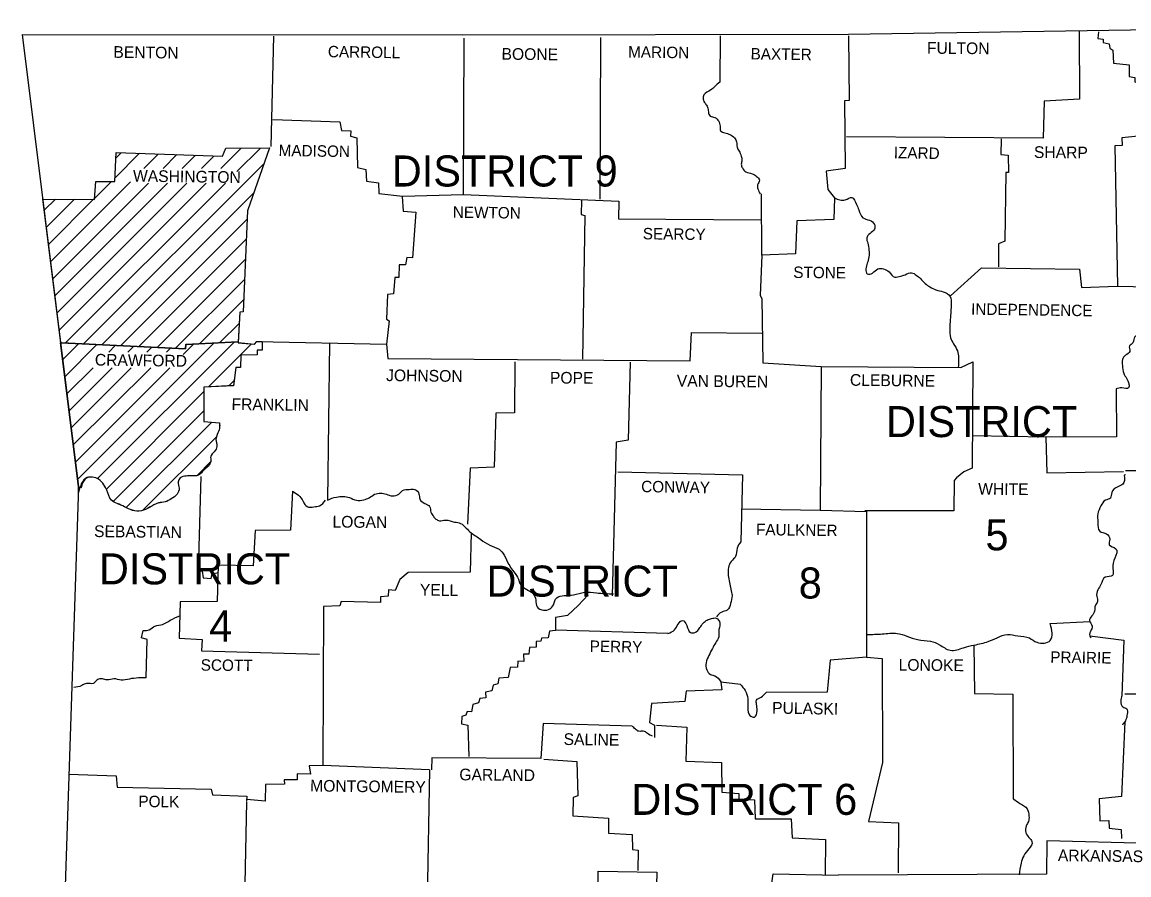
# Model space of a CAD drawing. Extents: x 21307 to 29830, y 1322443 to 1332359.
# Drawn here: x 24969 to 25700, y 1330891 to 1331455 of the extents above; entities that cross this region are included whole.
import ezdxf

# ---------------------------------------------------------------- set-up
doc = ezdxf.new("R2010")
doc.units = 0
doc.layers.add('R_Draft', color=7, linetype='Continuous')

msp = doc.modelspace()

# ---------------------------------------------------------------- linework, layer by layer
at = {"layer": 'R_Draft'}
for p, q in [((25698.3, 1331158.83), (25719.72, 1331158.83)), ((25238.04, 1330960.83), (25235.94, 1330847.79))]:
    msp.add_line(p, q, dxfattribs=at)
for points in [[(24968.58, 1331447.01), (25259.64, 1331446.83), (25515.06, 1331447.37), (25816.38, 1331452.05), (25956.06, 1331455.29)], [(24968.58, 1331447.01), (25005.84, 1331147.85), (24989.64, 1330659.51)], [(25134.72, 1331445.93), (25133.1, 1331373.03)], [(25134.36, 1331390.85), (25178.64, 1331389.41), (25179.72, 1331383.65), (25185.84, 1331383.47), (25185.66, 1331379.87), (25189.98, 1331378.79), (25190.34, 1331359.17), (25195.92, 1331357.91), (25196.28, 1331350.17), (25204.2, 1331349.09), (25204.56, 1331341.89), (25220.22, 1331340.27), (25260.54, 1331341.17), (25260.9, 1331444.67)], [(25351.08, 1331445.03), (25350.54, 1331338.11)], [(25430.28, 1331446.29), (25429.92, 1331415.51)], [(25515.06, 1331446.29), (25515.42, 1331403.45), (25512.36, 1331403.27), (25512.9, 1331358.45), (25500.3, 1331356.65), (25501.38, 1331344.59), (25505.7, 1331339.01), (25505.34, 1331324.79), (25480.86, 1331323.89), (25479.96, 1331301.93), (25457.64, 1331301.21), (25456.56, 1331274.57), (25457.82, 1331272.41), (25458.36, 1331229.93), (25496.88, 1331227.41), (25496.34, 1331132.55), (25526.94, 1331131.65), (25526.94, 1331035.17), (25502.82, 1331033.37), (25501.02, 1331012.13), (25460.52, 1331011.95)], [(25667.52, 1331448.99), (25667.88, 1331404.35), (25644.48, 1331403.09), (25643.76, 1331378.61), (25513.62, 1331379.33)], [(25680.48, 1331448.81), (25679.94, 1331444.49), (25683.54, 1331443.95), (25683.36, 1331441.79), (25687.5, 1331440.89), (25687.86, 1331438.01), (25689.84, 1331436.75), (25690.38, 1331428.11), (25700.64, 1331427.03), (25700.64, 1331419.29), (25704.42, 1331418.75), (25704.42, 1331415.69), (25707.66, 1331414.79), (25707.48, 1331404.35), (25710.36, 1331403.81), (25711.08, 1331380.23), (25695.78, 1331378.79), (25695.96, 1331373.75), (25691.28, 1331373.57), (25692.9, 1331280.69), (25765.44, 1331279.07), (25766.7, 1331134.71), (25719.36, 1331133.45), (25718.46, 1331157.75)], [(25616.04, 1331378.07), (25615.68, 1331367.63), (25620.72, 1331367.27), (25620.9, 1331355.75), (25619.1, 1331355.75), (25618.38, 1331310.39), (25614.24, 1331308.59), (25614.24, 1331293.47)], [(24982.8, 1331338.11), (25016.46, 1331337.93), (25017.36, 1331349.81), (25029.78, 1331349.81), (25030.86, 1331369.07), (25101.06, 1331366.55), (25103.22, 1331371.95), (25132.2, 1331372.13), (25117.62, 1331330.37), (25114.74, 1331263.59), (25112.58, 1331263.41), (25111.5, 1331243.25), (25122.12, 1331242.35), (25123.74, 1331243.97), (25209.6, 1331242.35), (25210.5, 1331232.81)], [(24982.8, 1331338.11), (25016.46, 1331337.93), (25017.36, 1331349.81), (25029.78, 1331349.81), (25030.86, 1331369.07), (25101.06, 1331366.55), (25103.22, 1331371.95), (25132.2, 1331372.13), (25117.62, 1331330.37), (25114.74, 1331263.59), (25112.58, 1331263.41), (25111.5, 1331243.79)], [(25099.98, 1331358.45), (25113.48, 1331371.95)], [(25110.6, 1331356.47), (25126.26, 1331371.95)], [(25029.96, 1331352.15), (25046.16, 1331368.53)], [(25030.68, 1331365.47), (25034.1, 1331368.89)], [(25049.04, 1331358.45), (25058.58, 1331367.99)], [(25061.82, 1331358.45), (25070.82, 1331367.63)], [(25074.42, 1331358.45), (25083.24, 1331367.27)], [(25087.2, 1331358.45), (25095.3, 1331366.73)], [(25009.26, 1331242.53), (25128.42, 1331361.51)], [(24987.48, 1331296.89), (25040.22, 1331349.63)], [(24988.92, 1331285.55), (25052.1, 1331348.73)], [(24990.36, 1331274.39), (25064.7, 1331348.73)], [(24991.8, 1331263.05), (25077.48, 1331348.73)], [(24993.24, 1331251.71), (25090.26, 1331348.73)], [(24997.2, 1331243.07), (25103.04, 1331348.73)], [(25016.64, 1331338.83), (25027.62, 1331349.81)], [(25021.5, 1331241.99), (25121.58, 1331342.07)], [(25260.54, 1331341.17), (25363.14, 1331336.85), (25362.96, 1331325.15), (25457.1, 1331324.43)], [(25457.64, 1331301.21), (25457.46, 1331341.71)], [(24994.14, 1331243.07), (24982.26, 1331338.11)], [(24983.16, 1331330.91), (24990.54, 1331338.11)], [(24984.6, 1331319.57), (25003.14, 1331338.11)], [(24986.04, 1331308.23), (25015.74, 1331338.11)], [(25219.86, 1331339.91), (25220.58, 1331330.19), (25228.86, 1331329.65), (25226.7, 1331299.41), (25222.92, 1331299.59), (25222.2, 1331294.73), (25217.88, 1331294.73), (25217.7, 1331286.45), (25215, 1331286.27), (25214.1, 1331275.65), (25210.14, 1331275.11), (25209.6, 1331258.91), (25211.4, 1331257.65), (25209.6, 1331242.35)], [(25338.48, 1331337.39), (25338.3, 1331328.03), (25340.64, 1331327.49), (25339.2, 1331232.45)], [(25033.56, 1331241.27), (25117.44, 1331324.97)], [(25045.8, 1331240.73), (25116.72, 1331311.65)], [(25058.04, 1331240.19), (25116.18, 1331298.51)], [(25582.56, 1331274.21), (25603.08, 1331292.75), (25667.88, 1331291.85), (25669.14, 1331279.79), (25692.72, 1331280.69)], [(25070.1, 1331239.65), (25115.64, 1331285.01)], [(25085.76, 1331242.53), (25114.92, 1331271.69)], [(25099.26, 1331243.43), (25112.22, 1331256.21)], [(25210.5, 1331232.81), (25410.3, 1331231.19), (25411.2, 1331250.09), (25457.64, 1331249.55)], [(24993.97, 1331243.1), (25076.59, 1331239.32), (25076.95, 1331242.2), (25111.15, 1331243.82)], [(25005.85, 1331144.28), (25005.85, 1331147.88), (24993.97, 1331243.1)], [(24994.68, 1331243.07), (25076.58, 1331239.29), (25076.94, 1331242.17), (25111.14, 1331243.79)], [(25111.5, 1331243.79), (25076.94, 1331242.17), (25076.58, 1331239.29), (24994.68, 1331243.07)], [(24995.41, 1331232.12), (25005.85, 1331242.56)], [(24996.85, 1331220.78), (25017.91, 1331242.02)], [(25005.31, 1331153.1), (25095.31, 1331242.92)], [(25018.45, 1331153.46), (25108.81, 1331243.64)], [(25025.83, 1331236.98), (25030.15, 1331241.3)], [(25038.43, 1331236.98), (25042.21, 1331240.76)], [(25051.03, 1331236.98), (25054.45, 1331240.4)], [(25063.99, 1331236.98), (25066.69, 1331239.68)], [(25074.97, 1331235.36), (25081.81, 1331242.2)], [(25127.34, 1331241.63), (25127.34, 1331238.39), (25123.92, 1331238.39), (25124.1, 1331235.15), (25113.12, 1331234.97), (25112.94, 1331226.87), (25109.88, 1331226.87), (25108.26, 1331214.81), (25088.82, 1331213.91), (25088.64, 1331191.05), (25099.08, 1331190.33)], [(25127.35, 1331244), (25127.35, 1331238.42), (25123.93, 1331238.42), (25124.11, 1331235.18), (25113.13, 1331235), (25112.95, 1331226.9), (25109.89, 1331226.9), (25108.27, 1331214.84), (25088.83, 1331213.94), (25088.65, 1331191.08), (25099.09, 1331190.36)], [(25091.89, 1331214.12), (25120.33, 1331242.56)], [(25111.51, 1331243.82), (25111.51, 1331243.28), (25122.13, 1331242.38), (25123.75, 1331244), (25127.35, 1331244)], [(25171.8, 1331243.07), (25170.54, 1331139.21)], [(24998.29, 1331209.62), (25015.57, 1331226.72)], [(24999.73, 1331198.28), (25028.17, 1331226.72)], [(25000.99, 1331186.94), (25040.77, 1331226.72)], [(25002.43, 1331175.6), (25053.73, 1331226.72)], [(25003.87, 1331164.26), (25066.33, 1331226.72)], [(25294.43, 1331230.53), (25294.25, 1331196.87), (25281.83, 1331196.69), (25280.75, 1331160.87), (25264.91, 1331160.33), (25263.11, 1331123.25)], [(25370.67, 1331230.34), (25369.35, 1331178.86), (25361.43, 1331177.54), (25358.79, 1331075.91)], [(25496.88, 1331227.41), (25589.4, 1331226.87), (25597.32, 1331230.65), (25596.78, 1331160.27), (25591.38, 1331157.93), (25586.52, 1331153.79), (25584.9, 1331152.17), (25584.72, 1331132.01), (25525.86, 1331132.01)], [(25105.21, 1331214.66), (25108.63, 1331218.08)], [(25024.39, 1331146.44), (25088.83, 1331210.88)], [(25692, 1331212.65), (25692.36, 1331180.97), (25645.56, 1331180.79), (25597.5, 1331181.69)], [(25028.89, 1331138.34), (25088.83, 1331198.28)], [(25037.53, 1331134.38), (25094.05, 1331190.72)], [(25048.33, 1331132.4), (25097.11, 1331181)], [(25645.56, 1331180.79), (25646.28, 1331157.21), (25696.86, 1331158.11)], [(25084.51, 1331155.62), (25093.33, 1331164.62)], [(25362.6, 1331157.93), (25444.86, 1331155.95), (25443.78, 1331111.49)], [(25086.84, 1331154.69), (25085.04, 1331092.77), (25087.74, 1331092.05), (25088.28, 1331087.73), (25093.68, 1331087.37), (25094.22, 1331090.43), (25098.54, 1331091.15)], [(25698.3, 1331155.77), (25697.4, 1331155.59)], [(25147.32, 1331144.97), (25146.06, 1331119.23), (25122.66, 1331119.05), (25121.4, 1331095.65), (25098.18, 1331096.19), (25097.46, 1331072.07), (25073.16, 1331071.89), (25072.44, 1331047.77), (25087.74, 1331046.87), (25087.2, 1331039.49), (25165.32, 1331037.33)], [(25443.96, 1331133.27), (25496.34, 1331132.55)], [(25766.7, 1331134.71), (25769.4, 1331036.07), (25726.56, 1331035.89), (25726.38, 1331031.93), (25713.96, 1331031.21), (25712.88, 1331010.69), (25697.76, 1331010.69)], [(25265.58, 1331117.43), (25264.86, 1331091.51), (25223.82, 1331091.33), (25218.42, 1331086.65), (25215.36, 1331079.45), (25210.86, 1331079.81), (25210.68, 1331075.67), (25205.46, 1331075.13), (25205.64, 1331071.35), (25179.54, 1331072.07), (25178.64, 1331069.19), (25167.84, 1331068.83), (25167.48, 1330963.78)], [(25342.8, 1331076.39), (25336.32, 1331069.37), (25329.3, 1331062.71), (25321.2, 1331061.45), (25321.2, 1331052.99), (25317.24, 1331052.45), (25316.52, 1331048.13), (25312.02, 1331047.77), (25311.66, 1331045.79), (25308.6, 1331045.61), (25308.42, 1331041.83), (25304.1, 1331041.65), (25303.74, 1331037.33), (25300.14, 1331037.33), (25300.32, 1331032.29), (25296.36, 1331032.65), (25296.18, 1331028.69), (25291.32, 1331028.33), (25289.88, 1331021.85), (25283.76, 1331021.31), (25283.22, 1331017.71), (25279.98, 1331016.81), (25279.08, 1331013.03), (25274.94, 1331012.13), (25275.3, 1331008.35), (25271.16, 1331007.99), (25270.44, 1331005.11), (25266.66, 1331004.03), (25265.76, 1330999.17), (25262.88, 1330999.35), (25261.98, 1330996.83), (25259.28, 1330995.93), (25259.1, 1330991.07), (25263.24, 1330990.35), (25263.96, 1330969.47)], [(25648.44, 1331057.49), (25674.54, 1331058.75)], [(25050.66, 1331021.67), (25051.2, 1331047.05), (25047.6, 1331048.13), (25048.68, 1331052.99)], [(25395.54, 1331050.83), (25321.38, 1331053.17)], [(25674.54, 1331049.39), (25697.04, 1331046.51), (25695.78, 1331009.79)], [(25598.04, 1331043.45), (25598.4, 1331011.23), (25623.78, 1331010.69), (25623.96, 1330941.57)], [(25526.94, 1331035.17), (25537.38, 1331034.45), (25537.56, 1330965.69), (25528.2, 1330926.63), (25548.18, 1330925.73), (25548, 1330892.61)], [(25443.6, 1331017.17), (25430.64, 1331018.61), (25431.18, 1331013.75), (25407.6, 1331012.85), (25406.88, 1331005.83), (25384.74, 1331004.57), (25383.48, 1330991.97), (25386.72, 1330990.35), (25386.72, 1330982.07)], [(25371.96, 1330989.63), (25313.1, 1330991.43), (25311.48, 1330968.21), (25239.48, 1330968.57), (25239.19, 1330960.79)], [(25387.98, 1330990.17), (25408.14, 1330988.91), (25407.42, 1330966.41), (25431, 1330965.51), (25431.36, 1330945.89), (25442.52, 1330944.99), (25442.52, 1330941.57), (25452.96, 1330940.85), (25453.32, 1330928.25), (25477.08, 1330928.25), (25477.8, 1330915.83), (25499.76, 1330914.75), (25499.58, 1330891.35)], [(25697.76, 1330992.51), (25695.6, 1330943.19), (25680.84, 1330941.57), (25681.2, 1330926.99), (25687.14, 1330927.17), (25687.32, 1330922.13), (25695.42, 1330921.23), (25695.6, 1330915.29)], [(25313.64, 1330967.85), (25335.42, 1330966.23), (25336.14, 1330943.55), (25333.08, 1330942.47), (25332.72, 1330930.41), (25356.3, 1330928.79), (25356.3, 1330918.89), (25371.96, 1330917.99), (25372.14, 1330908.09), (25375.92, 1330907.55), (25375.74, 1330894.23)], [(25167.48, 1330963.78), (25167.48, 1330963.53), (25158.48, 1330963.35), (25159.2, 1330957.95), (25150.56, 1330958.13), (25150.38, 1330954.17), (25141.92, 1330954.17), (25142.1, 1330951.29), (25129.5, 1330950.93), (25129.32, 1330939.95), (25117.09, 1330941.03)], [(25238.04, 1330960.83), (25167.48, 1330963.53)], [(24999.54, 1330957.95), (25030.68, 1330956.87), (25031.4, 1330949.31), (25093.68, 1330948.05), (25094.4, 1330944.09), (25117.08, 1330943.37), (25116.9, 1330939.95)], [(25117.05, 1330939.63), (25115.11, 1330852.83)], [(25714.32, 1330912.05), (25646.28, 1330913.85), (25645.92, 1330891.71), (25508.22, 1330891.17)], [(25236.24, 1330863.63), (25339.2, 1330862.19), (25341.18, 1330879.29), (25349.28, 1330879.29), (25349.46, 1330893.69), (25388.34, 1330893.15), (25387.98, 1330884.51), (25398.06, 1330883.79), (25398.06, 1330867.95), (25404.54, 1330867.41), (25404.46, 1330865.76)], [(25404.54, 1330867.41), (25414.62, 1330868.85), (25415.34, 1330874.97), (25421.28, 1330876.05), (25421.64, 1330879.65), (25463.58, 1330880.91), (25465.2, 1330891.89), (25508.22, 1330891.17)]]:
    msp.add_lwpolyline(points, dxfattribs=at)
for points in [[(25429.92, 1331415.51), (25426.68, 1331412.81), (25423.8, 1331410.29), (25419.48, 1331407.23), (25418.94, 1331404.35), (25420.38, 1331401.47), (25421.82, 1331399.13), (25422.36, 1331395.89), (25423.62, 1331393.19), (25426.68, 1331392.11), (25429.2, 1331389.77), (25430.1, 1331386.53), (25430.46, 1331383.47), (25433.34, 1331382.03), (25436.58, 1331380.95), (25439.64, 1331378.79), (25441.08, 1331376.09), (25441.44, 1331372.67), (25442.7, 1331369.97), (25444.14, 1331366.73), (25444.5, 1331364.03), (25444.14, 1331361.33), (25444.86, 1331358.81), (25447.2, 1331356.29), (25451.34, 1331355.03), (25454.22, 1331353.23), (25456.2, 1331350.71), (25454.94, 1331347.65), (25455.12, 1331344.95), (25456.74, 1331341.71)], [(25505.7, 1331339.01), (25512.9, 1331337.75), (25517.22, 1331339.37), (25520.28, 1331334.69), (25521.9, 1331331.09), (25524.6, 1331325.87), (25528.92, 1331324.25), (25532.16, 1331321.37), (25532.16, 1331318.31), (25529.28, 1331315.43), (25527.12, 1331312.55), (25527.84, 1331309.13), (25528.56, 1331304.45), (25528.56, 1331299.95), (25527.48, 1331295.81), (25526.58, 1331292.03), (25527.48, 1331288.79), (25530.9, 1331289.33), (25534.5, 1331292.03), (25538.28, 1331292.03), (25541.88, 1331290.05), (25545.66, 1331286.63), (25549.44, 1331287.35), (25552.5, 1331288.25), (25556.82, 1331289.51), (25559.88, 1331287.89), (25562.58, 1331285.73), (25565.82, 1331282.31), (25568.88, 1331280.15), (25572.84, 1331278.17), (25577.7, 1331276.91), (25582.2, 1331273.85), (25582.92, 1331268.63), (25582.74, 1331264.13), (25582.38, 1331258.55), (25582.02, 1331252.43), (25582.56, 1331246.49), (25584.54, 1331242.53), (25587.06, 1331237.85), (25587.78, 1331233.53), (25587.6, 1331226.69)], [(25724.22, 1331277.45), (25722.06, 1331271.87), (25719.54, 1331266.47), (25717.92, 1331261.79), (25714.5, 1331259.09), (25713.42, 1331256.57), (25710.36, 1331255.49), (25708.02, 1331251.89), (25706.94, 1331248.65), (25704.42, 1331247.21), (25703.16, 1331243.25), (25700.82, 1331241.09), (25701, 1331237.49), (25698.3, 1331234.97), (25696.14, 1331232.09), (25696.14, 1331228.13), (25697.04, 1331222.91), (25698.84, 1331219.85), (25700.46, 1331215.89), (25700.28, 1331213.37), (25695.78, 1331213.37), (25692, 1331212.65)], [(25099.09, 1331190.36), (25099.09, 1331186.58), (25097.65, 1331182.62), (25096.75, 1331179.2), (25097.29, 1331174.7), (25095.67, 1331171.1), (25093.33, 1331168.22), (25093.33, 1331164.62), (25090.63, 1331160.84), (25087.75, 1331157.96), (25085.23, 1331155.62), (25080.73, 1331155.26), (25076.95, 1331155.08), (25073.17, 1331153.82), (25071.73, 1331151.12), (25072.45, 1331146.98), (25071.01, 1331143.02), (25067.23, 1331139.96), (25063.09, 1331137.98), (25058.77, 1331137.26), (25052.83, 1331134.38), (25047.43, 1331132.04), (25041.67, 1331132.4), (25036.27, 1331134.74), (25031.41, 1331136.9), (25027.63, 1331139.06), (25024.57, 1331145.72), (25022.59, 1331149.32), (25019.17, 1331152.92), (25015.03, 1331154.36), (25011.61, 1331154), (25005.85, 1331144.28)], [(25099.08, 1331190.33), (25099.08, 1331186.55), (25097.64, 1331182.59), (25096.74, 1331179.17), (25097.28, 1331174.67), (25095.66, 1331171.07), (25093.32, 1331168.19), (25093.32, 1331164.59), (25090.62, 1331160.81), (25087.74, 1331157.93), (25085.22, 1331155.59), (25080.72, 1331155.23), (25076.94, 1331155.05), (25073.16, 1331153.79), (25071.72, 1331151.09), (25072.44, 1331146.95), (25071, 1331142.99), (25067.22, 1331139.93), (25063.08, 1331137.95), (25058.76, 1331137.23), (25052.82, 1331134.35), (25047.42, 1331132.01), (25041.66, 1331132.37), (25036.26, 1331134.71), (25031.4, 1331136.87), (25027.62, 1331139.03), (25024.56, 1331145.69), (25022.58, 1331149.29), (25019.16, 1331152.89), (25015.02, 1331154.33), (25011.6, 1331153.97), (25007.46, 1331146.95)], [(25697.4, 1331155.59), (25696.5, 1331149.65), (25693.08, 1331148.03), (25689.12, 1331144.07), (25688.22, 1331140.47), (25684.98, 1331139.03), (25681.92, 1331135.25), (25679.94, 1331130.03), (25679.94, 1331124.63), (25681.2, 1331118.51), (25685.7, 1331116.89), (25687.86, 1331113.29), (25687.5, 1331109.51), (25691.82, 1331106.99), (25692.54, 1331104.83), (25691.82, 1331102.49), (25689.84, 1331095.83), (25690.02, 1331091.33), (25689.66, 1331089.35), (25684.8, 1331088.09), (25681.92, 1331083.23), (25679.94, 1331079.81), (25679.22, 1331075.31), (25679.76, 1331072.07), (25678.32, 1331069.55), (25677.78, 1331065.77), (25675.98, 1331062.53), (25674.36, 1331059.47), (25676.16, 1331055.87), (25675.62, 1331053.35), (25674.54, 1331049.39), (25675.44, 1331048.13)], [(25147.32, 1331144.97), (25151.28, 1331142.45), (25154.34, 1331138.31), (25157.04, 1331134.89), (25161.54, 1331134.71), (25165.14, 1331135.43), (25169.28, 1331139.03)], [(25170.54, 1331139.21), (25176.48, 1331141.19), (25180.8, 1331141.55), (25185.12, 1331140.83), (25189.62, 1331139.03), (25194.48, 1331139.39), (25198.08, 1331140.65), (25201.68, 1331142.99), (25205.64, 1331143.71), (25209.42, 1331142.99), (25213.38, 1331141.91), (25217.7, 1331143.17), (25220.22, 1331145.51), (25224.54, 1331146.23), (25228.32, 1331146.23), (25231.02, 1331143.17), (25231.56, 1331139.93), (25234.98, 1331136.87), (25238.04, 1331134.89), (25238.94, 1331131.11), (25240.56, 1331128.41), (25242.18, 1331126.61), (25244.52, 1331125.53), (25248.48, 1331125.89), (25254.6, 1331124.63), (25258.56, 1331123.73), (25262.16, 1331120.67), (25265.58, 1331117.43)], [(25265.58, 1331117.43), (25271.88, 1331113.11), (25277.82, 1331109.33), (25283.94, 1331106.63), (25287.36, 1331102.67), (25290.42, 1331096.55), (25292.94, 1331092.77), (25296.18, 1331088.09), (25298.52, 1331082.87), (25302.3, 1331079.99), (25306.26, 1331077.47), (25308.24, 1331072.97), (25309.14, 1331068.47), (25313.46, 1331066.31), (25317.6, 1331067.21), (25319.94, 1331069.91), (25322.1, 1331074.59), (25326.96, 1331076.03), (25333.26, 1331076.57), (25340.46, 1331078.19), (25348.38, 1331077.83), (25359.54, 1331077.11)], [(25443.78, 1331111.49), (25441.44, 1331107.35), (25440.36, 1331101.95), (25437.48, 1331098.53), (25435.68, 1331094.57), (25435.5, 1331089.35), (25436.4, 1331084.67), (25437.3, 1331080.17), (25438.02, 1331076.03), (25437.12, 1331070.81), (25434.78, 1331066.31), (25431.18, 1331065.05), (25427.76, 1331061.99)], [(25048.68, 1331052.99), (25052.64, 1331053.35), (25056.42, 1331055.87), (25061.46, 1331056.95), (25066.5, 1331059.65), (25072.8, 1331062.53)], [(25395.54, 1331050.83), (25400.04, 1331053.35), (25402.38, 1331057.13), (25405.26, 1331059.47), (25408.14, 1331056.23), (25410.66, 1331051.55), (25413.36, 1331051.55), (25416.78, 1331054.79), (25418.94, 1331057.67), (25421.64, 1331059.83), (25424.52, 1331060.73), (25427.58, 1331061.09), (25429.92, 1331057.67), (25429.2, 1331052.27), (25429.2, 1331048.67), (25427.22, 1331044.89), (25425.06, 1331040.93), (25422.72, 1331036.43), (25420.92, 1331031.57), (25421.28, 1331026.89), (25423.8, 1331023.83), (25426.68, 1331022.93), (25430.64, 1331018.97)], [(25527.3, 1331050.29), (25537.38, 1331050.65), (25547.28, 1331051.01), (25553.58, 1331049.21), (25560.78, 1331046.87), (25569.24, 1331045.79), (25575.18, 1331043.45), (25582.2, 1331039.85), (25591.2, 1331041.47), (25598.22, 1331043.27), (25607.4, 1331045.61), (25613.34, 1331048.13), (25620.18, 1331050.29), (25627.02, 1331049.39), (25634.76, 1331047.95), (25639.62, 1331045.07), (25648.44, 1331046.33), (25648.44, 1331057.49)], [(25050.66, 1331021.67), (25045.44, 1331021.49), (25039.5, 1331020.77), (25034.1, 1331020.05), (25029.24, 1331020.95), (25024.74, 1331020.23), (25021.68, 1331020.95), (25017.9, 1331020.05), (25015.74, 1331017.89), (25011.24, 1331017.89), (25008, 1331016.45), (25002.78, 1331015.19)], [(25443.6, 1331017.17), (25446.66, 1331013.21), (25448.46, 1331007.81), (25448.46, 1331001.69), (25449.9, 1330996.65), (25452.78, 1330995.57), (25454.58, 1330999.89), (25454.22, 1331004.21), (25454.22, 1331006.73), (25457.28, 1331008.89), (25460.52, 1331011.95)], [(25695.78, 1331009.79), (25695.06, 1331006.19), (25696.5, 1331002.41), (25699.02, 1331001.15), (25699.38, 1330997.55), (25698.48, 1330993.95), (25697.76, 1330992.51), (25696.14, 1330990.35)], [(25385.46, 1330982.97), (25382.04, 1330984.77), (25379.34, 1330986.39), (25376.46, 1330986.21), (25374.12, 1330987.65), (25371.96, 1330989.63)], [(25623.96, 1330941.57), (25628.46, 1330938.51), (25633.14, 1330934.91), (25634.4, 1330930.05), (25634.04, 1330926.63), (25632.6, 1330923.75), (25632.24, 1330919.25), (25634.4, 1330916.01), (25636.38, 1330913.31), (25634.4, 1330908.45), (25630.98, 1330903.95), (25629.18, 1330898.91), (25627.92, 1330891.35)]]:
    msp.add_spline(points, degree=3, dxfattribs=at)

# ---------------------------------------------------------------- texts
for s, height, rotation, p in [('BENTON', 7.741, 359.25271, (25028.88, 1331431.71)), ('CARROLL', 7.561, 359.14808, (25170.72, 1331432.07)), ('BOONE', 7.741, 359.40007, (25285.56, 1331430.45)), ('MARION', 7.561, 359.18542, (25369.26, 1331431.89)), ('BAXTER', 7.561, 359.25594, (25450.26, 1331430.63)), ('FULTON', 7.739, 359.49961, (25566.9, 1331434.41)), ('MADISON', 7.561, 359.09062, (25138.14, 1331366.73)), ('IZARD', 7.559, 358.92583, (25544.94, 1331365.29)), ('SHARP', 7.739, 359.39049, (25637.64, 1331365.47)), ('WASHINGTON', 7.739, 359.23201, (25041.84, 1331349.81)), ('NEWTON', 7.561, 359.2717, (25253.34, 1331325.87)), ('SEARCY', 7.559, 359.25271, (25378.98, 1331311.65)), ('STONE', 7.559, 359.40007, (25478.52, 1331286.09)), ('INDEPENDENCE', 7.5588, 359.21874, (25596.06, 1331261.79)), ('CRAWFORD', 7.739, 359.27706, (25016.64, 1331228.13)), ('JOHNSON', 7.741, 359.3514, (25209.24, 1331217.87)), ('POPE', 7.741, 359.61547, (25317.6, 1331216.25)), ('VAN BUREN', 7.741, 359.35078, (25401.48, 1331214.27)), ('CLEBURNE', 7.739, 359.25352, (25515.96, 1331214.81)), ('FRANKLIN', 7.741, 359.18154, (25107, 1331198.79)), ('CONWAY', 7.559, 359.03714, (25377.9, 1331144.43)), ('WHITE', 7.741, 359.31386, (25600.74, 1331142.81)), ('LOGAN', 7.741, 359.39691, (25173.78, 1331121.03)), ('SEBASTIAN', 7.739, 359.28159, (25016.1, 1331114.73)), ('FAULKNER', 7.561, 359.24862, (25453.86, 1331115.99)), ('YELL', 7.741, 359.19871, (25231.56, 1331076.03)), ('PERRY', 7.561, 359.08578, (25343.88, 1331038.77)), ('SCOTT', 7.561, 359.40628, (25086.66, 1331026.35)), ('LONOKE', 7.741, 359.49742, (25548.18, 1331026.35)), ('PRAIRIE', 7.561, 359.21158, (25648.44, 1331031.57)), ('PULASKI', 7.741, 359.05305, (25464.48, 1330997.91)), ('SALINE', 7.741, 359.14914, (25326.6, 1330977.21)), ('GARLAND', 7.741, 359.36576, (25257.66, 1330953.81)), ('MONTGOMERY', 7.741, 359.29442, (25159.02, 1330946.43)), ('POLK', 7.559, 359.21518, (25045.44, 1330936.17)), ('ARKANSAS', 7.739, 359.26783, (25653.48, 1330900.35))]:
    msp.add_text(s, height=height, rotation=rotation, dxfattribs=at).set_placement(p)
for s, p in [('DISTRICT 9', (25213.02, 1331346.57)), ('DISTRICT', (25539.81, 1331180.81)), ('5', (25605.6, 1331105.91)), ('DISTRICT', (25019.34, 1331083.41)), ('DISTRICT', (25275.66, 1331075.31)), ('8', (25482.12, 1331074.05)), ('4', (25092.24, 1331045.61)), ('DISTRICT 6', (25371.42, 1330930.95))]:
    msp.add_text(s, height=20.52, dxfattribs=at).set_placement(p)

doc.saveas('drawing.dxf')
